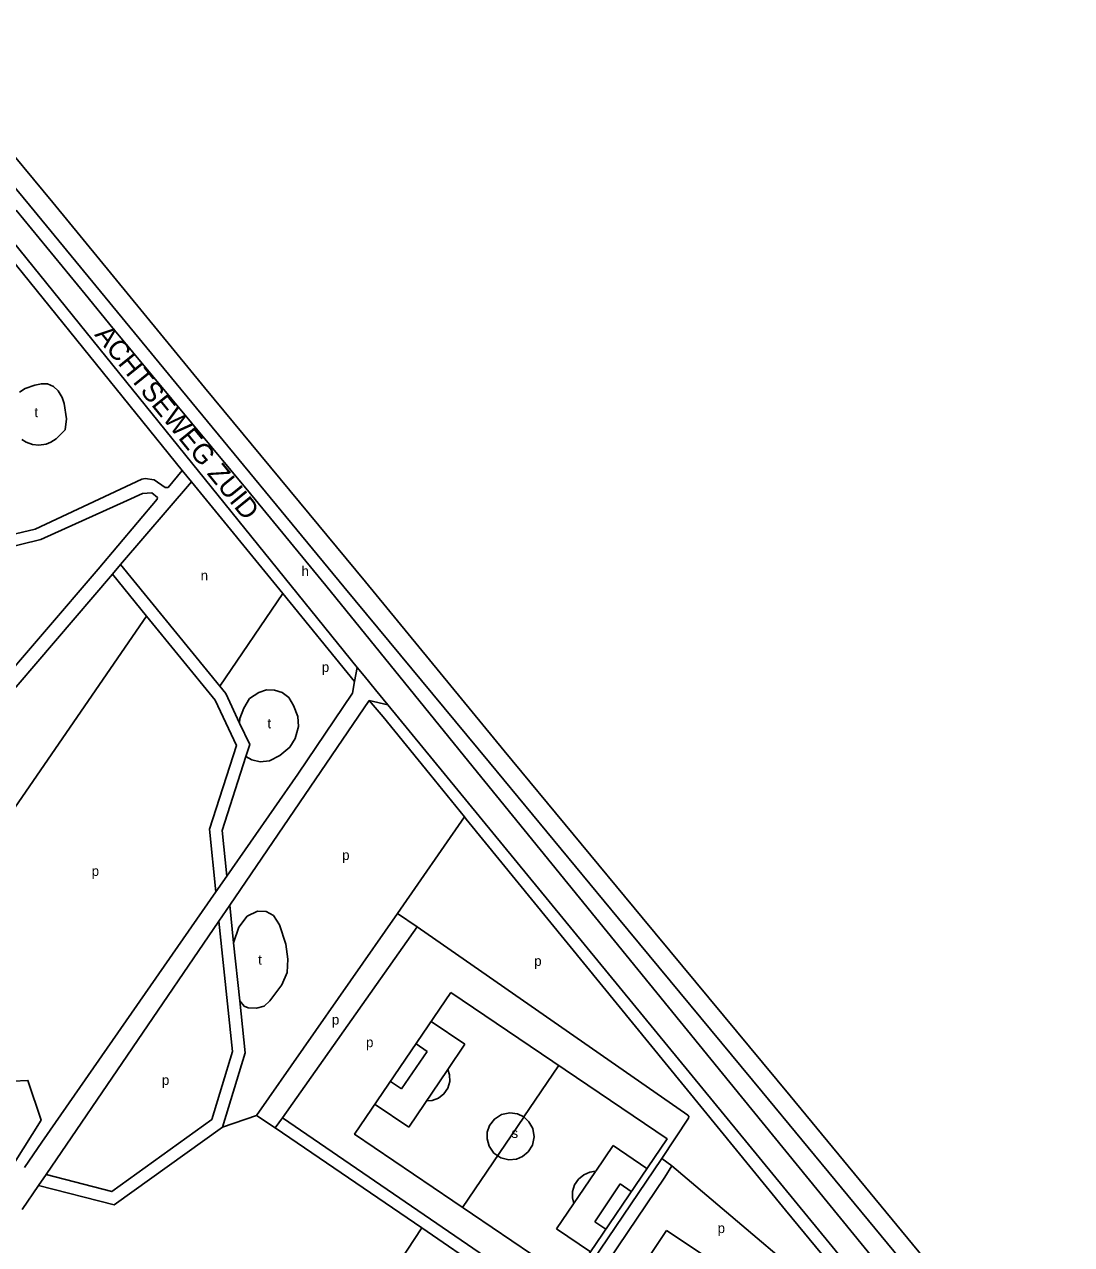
# Model space of a CAD drawing. Extents: x 157155 to 159285, y 385001 to 386651.
# Drawn here: x 158344.8 to 158766.6, y 385977 to 386468.8 of the extents above; entities that cross this region are included whole.
import ezdxf

# ---------------------------------------------------------------- set-up
doc = ezdxf.new("R2010")
doc.units = 0
for name, color, linetype in [('BLT_Basislijn', 7, 'Continuous'), ('BLT_Centroide', 7, 'Continuous'), ('BLT_Spoorlijn', 7, 'Continuous'), ('BLT_Straatnaam_hoofdweg', 7, 'Continuous')]:
    doc.layers.add(name, color=color, linetype=linetype)

msp = doc.modelspace()

# ---------------------------------------------------------------- linework, layer by layer
at = {"layer": 'BLT_Basislijn'}
for p, q in [((158310.02, 386410.57), (158408.29, 386288.97)), ((158341.46, 386393.95), (158369.3, 386360.01)), ((158369.3, 386360.01), (158380.41, 386346.4)), ((158380.41, 386346.4), (158435.8, 386279.61)), ((158412.16, 386284.45), (158408.29, 386288.97)), ((158448.82, 386239.41), (158412.16, 386284.45)), ((158435.8, 386279.61), (158466.18, 386242.62)), ((158394.01, 386230.3), (158380.24, 386247.19)), ((158466.18, 386242.62), (158523.82, 386171.63)), ((158448.82, 386239.41), (158477.78, 386203.92)), ((158421.65, 386196.39), (158394.01, 386230.3)), ((158477.78, 386203.92), (158478.87, 386209.66)), ((158478.87, 386209.66), (158481.63, 386206.25)), ((158476.9, 386199.26), (158477.78, 386203.92)), ((158481.63, 386206.25), (158486.2, 386200.54)), ((158486.2, 386200.54), (158491.12, 386194.55)), ((158483.66, 386196.26), (158491.12, 386194.55)), ((158491.12, 386194.55), (158766.6, 385858.7)), ((158523.82, 386171.63), (158574.88, 386108.78)), ((158522.06, 386149.41), (158495.08, 386110.51)), ((158438.31, 386029.02), (158495.08, 386110.51)), ((158502.93, 386105.05), (158495.08, 386110.51)), ((158448.74, 386028.15), (158502.93, 386105.05)), ((158574.88, 386108.78), (158633.61, 386036.53)), ((158522.23, 386057.76), (158508.66, 386066.94)), ((158507, 386054.86), (158502.53, 386057.89)), ((158522.23, 386057.76), (158515.38, 386047.64)), ((158507, 386054.86), (158496.75, 386039.73)), ((158515.35, 386047.6), (158499.61, 386024.35)), ((158559.93, 386049.06), (158546.01, 386028.49)), ((158496.75, 386039.73), (158492.28, 386042.75)), ((158633.61, 386036.53), (158695.48, 385960.83)), ((158499.61, 386024.35), (158486.04, 386033.54)), ((158438.31, 386029.02), (158424.53, 386024.39)), ((158445.75, 386024.03), (158438.31, 386029.02)), ((158445.75, 386024.03), (158448.74, 386028.15)), ((158545.97, 386028.43), (158521.31, 385992)), ((158445.75, 386024.03), (158504.83, 385983.72)), ((158581.89, 386016.9), (158574.91, 386006.59)), ((158595.51, 386007.68), (158581.89, 386016.9)), ((158601.59, 386011.77), (158605.54, 386008.81)), ((158574.87, 386006.53), (158559.18, 385983.37)), ((158584.81, 386001.44), (158574.53, 385986.25)), ((158589.25, 385998.44), (158584.81, 386001.44)), ((158448.74, 385898.35), (158504.83, 385983.72)), ((158572.81, 385974.15), (158559.18, 385983.37)), ((158578.97, 385983.25), (158574.53, 385986.25))]:
    msp.add_line(p, q, dxfattribs=at)
for points in [[(158313.6, 386414.08), (158478.87, 386209.66)], [(158342.81, 386320.54), (158345.03, 386322.1), (158348.95, 386323.32), (158351.65, 386323.95), (158354.1, 386323.88), (158356.57, 386322.84), (158358.44, 386321.07), (158359.94, 386318.47), (158360.74, 386315.97), (158361.78, 386309.79), (158361.14, 386305.43), (158357.57, 386301.75), (158355.42, 386300.4), (158353.52, 386299.61), (158350.61, 386299.21), (158348.03, 386299.51), (158345.5, 386300.4), (158343.71, 386301.55)], [(158283.92, 386249.87), (158349.06, 386265.38), (158392.15, 386285.56), (158393.49, 386285.72), (158396.99, 386285.27), (158401.53, 386282.17), (158402.65, 386282.18), (158408.29, 386288.97)], [(158383.55, 386251.05), (158412.16, 386284.45)], [(158290.06, 386246.17), (158351.36, 386261.24), (158386.23, 386276.93)], [(158386.23, 386276.93), (158392.38, 386279.69), (158396.07, 386279.96), (158398.42, 386278.11), (158398.26, 386277.41), (158374.55, 386249.18), (158331.09, 386198.74)], [(158270.21, 386049.42), (158264.8, 386055.47), (158238.53, 386078.74), (158237.42, 386080.12), (158237.46, 386080.53), (158311.26, 386166.67), (158380.24, 386247.19)], [(158380.24, 386247.19), (158383.55, 386251.05)], [(158423.48, 386202.06), (158383.55, 386251.05)], [(158423.48, 386202.06), (158448.82, 386239.41)], [(158394.01, 386230.3), (158301.04, 386095.3), (158333.47, 386074.41), (158340.16, 386042.87), (158346.17, 386043.2), (158351.52, 386027.15), (158340.62, 386009.77)], [(158431.47, 386187.2), (158425.92, 386199.07), (158423.48, 386202.06)], [(158426.29, 386125.51), (158454.88, 386166.67), (158476.9, 386199.26)], [(158433.97, 386173.68), (158436.41, 386172.39), (158439.69, 386171.6), (158443.46, 386171.94), (158447.73, 386174.07), (158451.66, 386177.55), (158453.87, 386181.02), (158455.13, 386185.82), (158454.89, 386189.81), (158453.21, 386194.33), (158451.25, 386197.52), (158448.66, 386199.48), (158445.54, 386200.4), (158442.29, 386200.57), (158439.23, 386199.47), (158435.41, 386197.1), (158433.11, 386193.24), (158431.51, 386189.03), (158431.47, 386187.2)], [(158421.92, 386119.22), (158419.31, 386144.4), (158430.17, 386178.19), (158421.65, 386196.39)], [(158427.5, 386113.83), (158483.66, 386196.26)], [(158522.06, 386149.41), (158508.06, 386166.67), (158489.32, 386189.71), (158483.66, 386196.26)], [(158433.97, 386173.68), (158435.53, 386178.53), (158431.47, 386187.2)], [(158426.29, 386125.51), (158424.39, 386143.87), (158433.97, 386173.68)], [(158522.06, 386149.41), (158522.79, 386148.46), (158651.38, 385990.95), (158756.98, 385862.92)], [(158421.92, 386119.22), (158426.29, 386125.51)], [(158351.79, 386018.27), (158421.92, 386119.22)], [(158423.14, 386107.42), (158427.5, 386113.83)], [(158429.07, 386098.69), (158427.5, 386113.83)], [(158431.5, 386075.3), (158433.25, 386073.16), (158434.9, 386072.41), (158438.34, 386072.35), (158441.3, 386073.08), (158443.69, 386075.32), (158448.53, 386081.71), (158450.58, 386086.66), (158450.96, 386092), (158450.07, 386098.03), (158447.59, 386105.94), (158445.17, 386109.62), (158442.15, 386111.27), (158438.72, 386111.37), (158434.58, 386109.34), (158431.18, 386104.95), (158429.07, 386098.69)], [(158353.51, 386005.23), (158379.94, 385998.4), (158420.24, 386027.46), (158428.59, 386054.85), (158423.14, 386107.42)], [(158353.51, 386005.23), (158423.14, 386107.42)], [(158601.59, 386011.77), (158612.32, 386027.96), (158612.41, 386028.69), (158612, 386029.12), (158502.93, 386105.05)], [(158431.5, 386075.3), (158429.07, 386098.69)], [(158424.53, 386024.39), (158433.67, 386054.36), (158431.5, 386075.3)], [(158515.37, 386047.62), (158516.06, 386045.39), (158516.12, 386042.79), (158515.35, 386040.1), (158513.74, 386037.73), (158511.53, 386036.01), (158509.09, 386035.1), (158506.76, 386034.92)], [(158601.59, 386011.77), (158561.14, 385951.93), (158560.35, 385951.65), (158448.74, 386028.15)], [(158545.95, 386028.47), (158543.45, 386029.69), (158540.33, 386030.13), (158537.02, 386029.44), (158534.13, 386027.61), (158532.16, 386025.03), (158531.23, 386022.27), (158531.15, 386019.57), (158531.97, 386016.65), (158533.87, 386013.92), (158536.7, 386011.98), (158539.92, 386011.17), (158542.95, 386011.44), (158545.44, 386012.48), (158547.69, 386014.34), (158549.39, 386017.1), (158550.08, 386020.45), (158549.54, 386023.79), (158548.02, 386026.55), (158545.98, 386028.45)], [(158350.52, 386000.84), (158380.96, 385992.97), (158424.53, 386024.39)], [(158344.79, 386008.05), (158351.79, 386018.27)], [(158605.54, 386008.81), (158602.79, 386004.25), (158531.21, 385898.12), (158528.99, 385894.46), (158534.09, 385891.2), (158605.58, 385841.25), (158610.2, 385838.34)], [(158574.88, 386006.55), (158572.54, 386006.21), (158570.15, 386005.19), (158568.01, 386003.44), (158566.42, 386001.11), (158565.6, 385998.47), (158565.54, 385995.87), (158566.09, 385993.57)], [(158667.29, 385921.7), (158682.04, 385942.77), (158682.27, 385943.78), (158605.54, 386008.81)], [(158350.52, 386000.84), (158353.51, 386005.23)], [(158343.91, 385991.14), (158350.52, 386000.84)], [(158504.83, 385983.72), (158557.27, 385947.82), (158557.8, 385947.74), (158554.76, 385942.71)]]:
    msp.add_lwpolyline(points, dxfattribs=at)
for points in [[(158516.51, 386078.63), (158603.66, 386019.63), (158564.95, 385962.46), (158477.81, 386021.46)], [(158603.48, 385982.71), (158541.79, 385890.22), (158601.72, 385850.25), (158663.41, 385942.74)]]:
    msp.add_lwpolyline(points, close=True, dxfattribs=at)
at = {"layer": 'BLT_Spoorlijn'}
for points in [[(158286.54, 386468.78), (158346.84, 386395.91)], [(158308.06, 386455.08), (158356.23, 386397)], [(158346.84, 386395.91), (158405.88, 386324.12)], [(158356.23, 386397), (158417.32, 386322.4)], [(158405.88, 386324.12), (158473.39, 386242.16)], [(158417.32, 386322.4), (158482.16, 386244.19)], [(158482.16, 386244.19), (158538.07, 386176.02)], [(158473.39, 386242.16), (158532.12, 386171.31)], [(158538.07, 386176.02), (158593.67, 386108.78)], [(158532.12, 386171.31), (158584.12, 386108.47)], [(158584.12, 386108.47), (158641.91, 386038.56)], [(158593.67, 386108.78), (158653.19, 386037)], [(158641.91, 386038.56), (158705.82, 385961.14)], [(158653.19, 386037), (158717.72, 385958.79)]]:
    msp.add_lwpolyline(points, dxfattribs=at)

# ---------------------------------------------------------------- texts
at = {"layer": 'BLT_Centroide'}
for s, p in [('t', (158348.83, 386310.49)), ('n', (158415.79, 386244.72)), ('h', (158456.4, 386246.45)), ('p', (158464.59, 386207.79)), ('t', (158442.68, 386185.05)), ('p', (158472.77, 386132)), ('p', (158371.89, 386125.58)), ('t', (158438.94, 386089.85)), ('p', (158550.15, 386089.34)), ('p', (158468.65, 386065.69)), ('p', (158482.4, 386056.57)), ('p', (158400.18, 386041.35)), ('s', (158540.99, 386019.98)), ('p', (158624.02, 385981.65))]:
    msp.add_text(s, height=4, dxfattribs=at).set_placement(p)
at = {"layer": 'BLT_Straatnaam_hoofdweg'}
msp.add_text('ACHTSEWEG ZUID', height=8, rotation=309.0181, dxfattribs=at).set_placement((158372.81, 386343.63))

doc.saveas('drawing.dxf')
